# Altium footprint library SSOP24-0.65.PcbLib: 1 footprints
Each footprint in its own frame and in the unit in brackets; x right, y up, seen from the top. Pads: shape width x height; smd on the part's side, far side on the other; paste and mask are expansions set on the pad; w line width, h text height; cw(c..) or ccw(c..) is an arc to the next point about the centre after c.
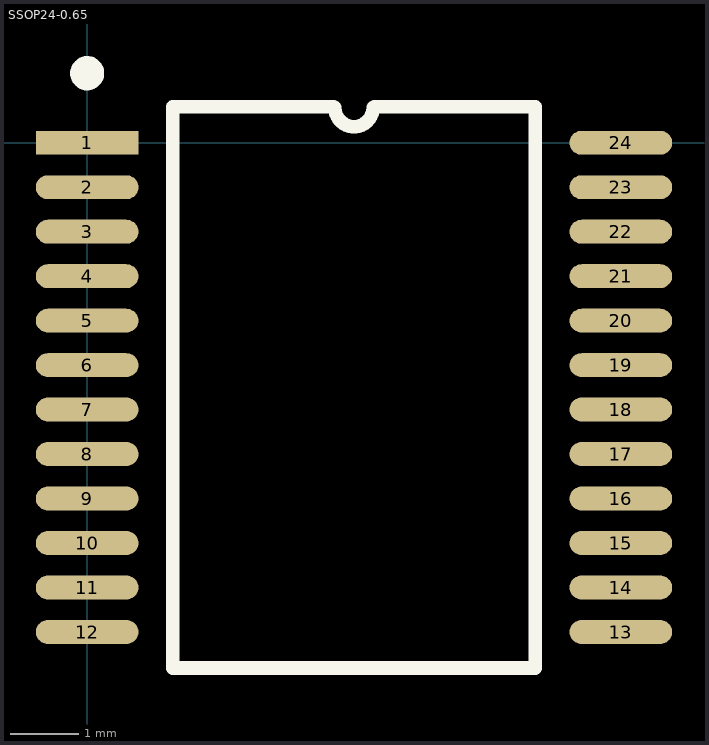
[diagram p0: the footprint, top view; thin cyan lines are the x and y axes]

## SSOP24-0.65 [mm]
pads (24):
  rect 1.5x0.35 smd: 1(0,0)
  oval 1.5x0.35 smd: 2(0,-0.65) 3(0,-1.3) 4(0,-1.95) 5(0,-2.6) 6(0,-3.25) 7(0,-3.9) 8(0,-4.55) 9(0,-5.2) 10(0,-5.85) 11(0,-6.5) 12(0,-7.15) 13(7.8,-7.15) 14(7.8,-6.5) 15(7.8,-5.85) 16(7.8,-5.2) 17(7.8,-4.55) 18(7.8,-3.9) 19(7.8,-3.25) 20(7.8,-2.6) 21(7.8,-1.95) 22(7.8,-1.3) 23(7.8,-0.65) 24(7.8,0)
Top Overlay:
  circle w0.25: c0,1.016 r0.125
  lines w0.2: 3.6,0.525 1.25,0.525 1.25,-7.675 6.55,-7.675 6.55,0.525 4.2,0.525 ; 3.619,0.514 ccw(c3.899,0.514) 4.179,0.514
